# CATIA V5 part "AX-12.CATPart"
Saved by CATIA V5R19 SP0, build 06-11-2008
Part number: DX124_DUMMY
Revision: 27
Definition: design
Nomenclature: DX124_DUMMY
Source: made
Description: NOT SPECIFIED
Bounding box of the stored display mesh (mm): x -16 to 16, y -38.5 to 11.5, z -19 to 21.7
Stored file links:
  C:\Users\Rémi\Documents\BTS CPI\Projet 04- Guitar Elec\Maquette 3D\Moteur\AX-12.CATPart
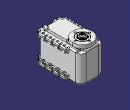
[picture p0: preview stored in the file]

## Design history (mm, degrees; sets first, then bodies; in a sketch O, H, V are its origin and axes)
Set1
  DatumSurface1 "CURVE_BOUNDED_SURFACE #7207"
  DatumSurface2 "CURVE_BOUNDED_SURFACE #7250"
  DatumSurface3 "CURVE_BOUNDED_SURFACE #7292"
  DatumSurface4 "CURVE_BOUNDED_SURFACE #7334"
  DatumSurface5 "CURVE_BOUNDED_SURFACE #7375"
  DatumSurface6 "CURVE_BOUNDED_SURFACE #7451"
  DatumSurface7 "CURVE_BOUNDED_SURFACE #7526"
  DatumSurface8 "CURVE_BOUNDED_SURFACE #7737"
  DatumSurface9 "CURVE_BOUNDED_SURFACE #7833"
  DatumSurface10 "CURVE_BOUNDED_SURFACE #7875"
  DatumSurface11 "CURVE_BOUNDED_SURFACE #7970"
  DatumSurface12 "CURVE_BOUNDED_SURFACE #8046"
  DatumSurface13 "CURVE_BOUNDED_SURFACE #8088"
  DatumSurface14 "CURVE_BOUNDED_SURFACE #8129"
  DatumSurface15 "CURVE_BOUNDED_SURFACE #8204"
  DatumSurface16 "CURVE_BOUNDED_SURFACE #8245"
  DatumSurface17 "CURVE_BOUNDED_SURFACE #8286"
  DatumSurface18 "CURVE_BOUNDED_SURFACE #8361"
  DatumSurface19 "CURVE_BOUNDED_SURFACE #9345"
  DatumSurface20 "CURVE_BOUNDED_SURFACE #9397"
  DatumSurface21 "CURVE_BOUNDED_SURFACE #9488"
  DatumSurface22 "CURVE_BOUNDED_SURFACE #9579"
  DatumSurface23 "CURVE_BOUNDED_SURFACE #9670"
  DatumSurface24 "CURVE_BOUNDED_SURFACE #9761"
  DatumSurface25 "CURVE_BOUNDED_SURFACE #9851"
  DatumSurface26 "CURVE_BOUNDED_SURFACE #9929"
  DatumSurface27 "CURVE_BOUNDED_SURFACE #10008"
  DatumSurface28 "CURVE_BOUNDED_SURFACE #10058"
  DatumSurface29 "CURVE_BOUNDED_SURFACE #10131"
  DatumSurface30 "CURVE_BOUNDED_SURFACE #10210"
  DatumSurface31 "CURVE_BOUNDED_SURFACE #10289"
  DatumSurface32 "CURVE_BOUNDED_SURFACE #10368"
  DatumSurface33 "CURVE_BOUNDED_SURFACE #10429"
  DatumSurface34 "CURVE_BOUNDED_SURFACE #10500"
  DatumSurface35 "CURVE_BOUNDED_SURFACE #10573"
  DatumSurface36 "CURVE_BOUNDED_SURFACE #10652"
  DatumSurface37 "CURVE_BOUNDED_SURFACE #10731"
  DatumSurface38 "CURVE_BOUNDED_SURFACE #10810"
  DatumSurface39 "CURVE_BOUNDED_SURFACE #10871"
  DatumSurface40 "CURVE_BOUNDED_SURFACE #10943"
  DatumSurface41 "CURVE_BOUNDED_SURFACE #10985"
  DatumSurface42 "CURVE_BOUNDED_SURFACE #11027"
  DatumSurface43 "CURVE_BOUNDED_SURFACE #11077"
  DatumSurface44 "CURVE_BOUNDED_SURFACE #11153"
  DatumSurface45 "CURVE_BOUNDED_SURFACE #11230"
  DatumSurface46 "CURVE_BOUNDED_SURFACE #11307"
  DatumSurface47 "CURVE_BOUNDED_SURFACE #11384"
  DatumSurface48 "CURVE_BOUNDED_SURFACE #11460"
  DatumSurface49 "CURVE_BOUNDED_SURFACE #11958"
  DatumSurface50 "CURVE_BOUNDED_SURFACE #12121"
  DatumSurface51 "CURVE_BOUNDED_SURFACE #12250"
  DatumSurface52 "CURVE_BOUNDED_SURFACE #12382"
  DatumSurface53 "CURVE_BOUNDED_SURFACE #12492"
  DatumSurface54 "CURVE_BOUNDED_SURFACE #12532"
  DatumSurface55 "CURVE_BOUNDED_SURFACE #12571"
  DatumSurface56 "CURVE_BOUNDED_SURFACE #12683"
  DatumSurface57 "CURVE_BOUNDED_SURFACE #12743"
  DatumSurface58 "CURVE_BOUNDED_SURFACE #12800"
  DatumSurface59 "CURVE_BOUNDED_SURFACE #12871"
  DatumSurface60 "CURVE_BOUNDED_SURFACE #12949"
  DatumSurface61 "CURVE_BOUNDED_SURFACE #13027"
  DatumSurface62 "CURVE_BOUNDED_SURFACE #13105"
  DatumSurface63 "CURVE_BOUNDED_SURFACE #13165"
  DatumSurface64 "CURVE_BOUNDED_SURFACE #13236"
  DatumSurface65 "CURVE_BOUNDED_SURFACE #13309"
  DatumSurface66 "CURVE_BOUNDED_SURFACE #13388"
  DatumSurface67 "CURVE_BOUNDED_SURFACE #13467"
  DatumSurface68 "CURVE_BOUNDED_SURFACE #13546"
  DatumSurface69 "CURVE_BOUNDED_SURFACE #13607"
  DatumSurface70 "CURVE_BOUNDED_SURFACE #13679"
  DatumSurface71 "CURVE_BOUNDED_SURFACE #13721"
  DatumSurface72 "CURVE_BOUNDED_SURFACE #13761"
  DatumSurface73 "CURVE_BOUNDED_SURFACE #13812"
  DatumSurface74 "CURVE_BOUNDED_SURFACE #13888"
  DatumSurface75 "CURVE_BOUNDED_SURFACE #13965"
  DatumSurface76 "CURVE_BOUNDED_SURFACE #14042"
  DatumSurface77 "CURVE_BOUNDED_SURFACE #14119"
  DatumSurface78 "CURVE_BOUNDED_SURFACE #14208"
  DatumSurface79 "CURVE_BOUNDED_SURFACE #14298"
  DatumSurface80 "CURVE_BOUNDED_SURFACE #14388"
  DatumSurface81 "CURVE_BOUNDED_SURFACE #14478"
  DatumSurface82 "CURVE_BOUNDED_SURFACE #14568"
  DatumSurface83 "CURVE_BOUNDED_SURFACE #14617"
  DatumSurface84 "CURVE_BOUNDED_SURFACE #14690"
  DatumSurface85 "CURVE_BOUNDED_SURFACE #14765"
  DatumSurface86 "CURVE_BOUNDED_SURFACE #14840"
  DatumSurface87 "CURVE_BOUNDED_SURFACE #14915"
  DatumSurface88 "CURVE_BOUNDED_SURFACE #14989"
  DatumSurface89 "CURVE_BOUNDED_SURFACE #15029"
  DatumSurface90 "CURVE_BOUNDED_SURFACE #15068"
  DatumSurface91 "CURVE_BOUNDED_SURFACE #15118"
  DatumSurface92 "CURVE_BOUNDED_SURFACE #15170"
  DatumSurface93 "CURVE_BOUNDED_SURFACE #15199"
  DatumSurface94 "CURVE_BOUNDED_SURFACE #15229"
  DatumSurface95 "CURVE_BOUNDED_SURFACE #15259"
  DatumSurface96 "CURVE_BOUNDED_SURFACE #15289"
  DatumSurface97 "CURVE_BOUNDED_SURFACE #15320"
  DatumSurface98 "CURVE_BOUNDED_SURFACE #15369"
  DatumSurface99 "CURVE_BOUNDED_SURFACE #15421"
  DatumSurface100 "CURVE_BOUNDED_SURFACE #15471"
  DatumSurface101 "CURVE_BOUNDED_SURFACE #16436"
  DatumSurface102 "CURVE_BOUNDED_SURFACE #16487"
  DatumSurface103 "CURVE_BOUNDED_SURFACE #16536"
  DatumSurface104 "CURVE_BOUNDED_SURFACE #16585"
  DatumSurface105 "CURVE_BOUNDED_SURFACE #16636"
  DatumSurface106 "CURVE_BOUNDED_SURFACE #16685"
  DatumSurface107 "CURVE_BOUNDED_SURFACE #16734"
  DatumSurface108 "CURVE_BOUNDED_SURFACE #16783"
  DatumSurface109 "CURVE_BOUNDED_SURFACE #16834"
  DatumSurface110 "CURVE_BOUNDED_SURFACE #16887"
  DatumSurface111 "CURVE_BOUNDED_SURFACE #16940"
  DatumSurface112 "CURVE_BOUNDED_SURFACE #16992"
  DatumSurface113 "CURVE_BOUNDED_SURFACE #17083"
  DatumSurface114 "CURVE_BOUNDED_SURFACE #17174"
  DatumSurface115 "CURVE_BOUNDED_SURFACE #17265"
  DatumSurface116 "CURVE_BOUNDED_SURFACE #17355"
  DatumSurface117 "CURVE_BOUNDED_SURFACE #17446"
  DatumSurface118 "CURVE_BOUNDED_SURFACE #17522"
  DatumSurface119 "CURVE_BOUNDED_SURFACE #17598"
  DatumSurface120 "CURVE_BOUNDED_SURFACE #17674"
  DatumSurface121 "CURVE_BOUNDED_SURFACE #17750"
  DatumSurface122 "CURVE_BOUNDED_SURFACE #17799"
  DatumSurface123 "CURVE_BOUNDED_SURFACE #17840"
  DatumSurface124 "CURVE_BOUNDED_SURFACE #17915"
  DatumSurface125 "CURVE_BOUNDED_SURFACE #17992"
  DatumSurface126 "CURVE_BOUNDED_SURFACE #18069"
  DatumSurface127 "CURVE_BOUNDED_SURFACE #18146"
  DatumSurface128 "CURVE_BOUNDED_SURFACE #18221"
  DatumSurface129 "CURVE_BOUNDED_SURFACE #18714"
  DatumSurface130 "CURVE_BOUNDED_SURFACE #18789"
  DatumSurface131 "CURVE_BOUNDED_SURFACE #18864"
  DatumSurface132 "CURVE_BOUNDED_SURFACE #18939"
  DatumSurface133 "CURVE_BOUNDED_SURFACE #19014"
  DatumSurface134 "CURVE_BOUNDED_SURFACE #19089"
  DatumSurface135 "CURVE_BOUNDED_SURFACE #19139"
  DatumSurface136 "CURVE_BOUNDED_SURFACE #19215"
  DatumSurface137 "CURVE_BOUNDED_SURFACE #19292"
  DatumSurface138 "CURVE_BOUNDED_SURFACE #19369"
  DatumSurface139 "CURVE_BOUNDED_SURFACE #19446"
  DatumSurface140 "CURVE_BOUNDED_SURFACE #19536"
  DatumSurface141 "CURVE_BOUNDED_SURFACE #19625"
  DatumSurface142 "CURVE_BOUNDED_SURFACE #19715"
  DatumSurface143 "CURVE_BOUNDED_SURFACE #19805"
  DatumSurface144 "CURVE_BOUNDED_SURFACE #19895"
  DatumSurface145 "CURVE_BOUNDED_SURFACE #19943"
  DatumSurface146 "CURVE_BOUNDED_SURFACE #19983"
  DatumSurface147 "CURVE_BOUNDED_SURFACE #20023"
  DatumSurface148 "CURVE_BOUNDED_SURFACE #20128"
  DatumSurface149 "CURVE_BOUNDED_SURFACE #20168"
  DatumSurface150 "CURVE_BOUNDED_SURFACE #20208"
  DatumSurface151 "CURVE_BOUNDED_SURFACE #20256"
  DatumSurface152 "CURVE_BOUNDED_SURFACE #20330"
  DatumSurface153 "CURVE_BOUNDED_SURFACE #20404"
  DatumSurface154 "CURVE_BOUNDED_SURFACE #20444"
  DatumSurface155 "CURVE_BOUNDED_SURFACE #20502"
  DatumSurface156 "CURVE_BOUNDED_SURFACE #20559"
  DatumSurface157 "CURVE_BOUNDED_SURFACE #20598"
  DatumSurface158 "CURVE_BOUNDED_SURFACE #20639"
  DatumSurface159 "CURVE_BOUNDED_SURFACE #20680"
  DatumSurface160 "CURVE_BOUNDED_SURFACE #20730"
  DatumSurface161 "CURVE_BOUNDED_SURFACE #20769"
  DatumSurface162 "CURVE_BOUNDED_SURFACE #20819"
  DatumSurface163 "CURVE_BOUNDED_SURFACE #20858"
  DatumSurface164 "CURVE_BOUNDED_SURFACE #20906"
  DatumSurface165 "CURVE_BOUNDED_SURFACE #20946"
  DatumSurface166 "CURVE_BOUNDED_SURFACE #20985"
  DatumSurface167 "CURVE_BOUNDED_SURFACE #21043"
  DatumSurface168 "CURVE_BOUNDED_SURFACE #21101"
  DatumSurface169 "CURVE_BOUNDED_SURFACE #21153"
  DatumSurface170 "CURVE_BOUNDED_SURFACE #21311"
  DatumSurface171 "CURVE_BOUNDED_SURFACE #21352"
  DatumSurface172 "CURVE_BOUNDED_SURFACE #21394"
  DatumSurface173 "CURVE_BOUNDED_SURFACE #21435"
  DatumSurface174 "CURVE_BOUNDED_SURFACE #21486"
  DatumSurface175 "CURVE_BOUNDED_SURFACE #21542"
  DatumSurface176 "CURVE_BOUNDED_SURFACE #21599"
  DatumSurface177 "CURVE_BOUNDED_SURFACE #21639"
  DatumSurface178 "CURVE_BOUNDED_SURFACE #21696"
  DatumSurface179 "CURVE_BOUNDED_SURFACE #21754"
  DatumSurface180 "CURVE_BOUNDED_SURFACE #21795"
  DatumSurface181 "CURVE_BOUNDED_SURFACE #21852"
  DatumSurface182 "CURVE_BOUNDED_SURFACE #21910"
  DatumSurface183 "CURVE_BOUNDED_SURFACE #21950"
  DatumSurface184 "CURVE_BOUNDED_SURFACE #22007"
  DatumSurface185 "CURVE_BOUNDED_SURFACE #22065"
  DatumSurface186 "CURVE_BOUNDED_SURFACE #22106"
  DatumSurface187 "CURVE_BOUNDED_SURFACE #22163"
  DatumSurface188 "CURVE_BOUNDED_SURFACE #22221"
  DatumSurface189 "CURVE_BOUNDED_SURFACE #22261"
  DatumSurface190 "CURVE_BOUNDED_SURFACE #22318"
  DatumSurface191 "CURVE_BOUNDED_SURFACE #22376"
  DatumSurface192 "CURVE_BOUNDED_SURFACE #22417"
  DatumSurface193 "CURVE_BOUNDED_SURFACE #22474"
  DatumSurface194 "CURVE_BOUNDED_SURFACE #22532"
  DatumSurface195 "CURVE_BOUNDED_SURFACE #22572"
  DatumSurface196 "CURVE_BOUNDED_SURFACE #22630"
  DatumSurface197 "CURVE_BOUNDED_SURFACE #22689"
  DatumSurface198 "CURVE_BOUNDED_SURFACE #22746"
  DatumSurface199 "CURVE_BOUNDED_SURFACE #22804"
  DatumSurface200 "CURVE_BOUNDED_SURFACE #22845"
  DatumSurface201 "CURVE_BOUNDED_SURFACE #22907"
  DatumSurface202 "CURVE_BOUNDED_SURFACE #22955"
  DatumSurface203 "CURVE_BOUNDED_SURFACE #23044"
  DatumSurface204 "CURVE_BOUNDED_SURFACE #23111"
  DatumSurface205 "CURVE_BOUNDED_SURFACE #23158"
  DatumSurface206 "CURVE_BOUNDED_SURFACE #23205"
  DatumSurface207 "CURVE_BOUNDED_SURFACE #23259"
  DatumSurface208 "CURVE_BOUNDED_SURFACE #23314"
  DatumSurface209 "CURVE_BOUNDED_SURFACE #23383"
  DatumSurface210 "CURVE_BOUNDED_SURFACE #23505"
  DatumSurface211 "CURVE_BOUNDED_SURFACE #23547"
  DatumSurface212 "CURVE_BOUNDED_SURFACE #23589"
  DatumSurface213 "CURVE_BOUNDED_SURFACE #23647"
  DatumSurface214 "CURVE_BOUNDED_SURFACE #23827"
  DatumSurface215 "CURVE_BOUNDED_SURFACE #23877"
  DatumSurface216 "CURVE_BOUNDED_SURFACE #23932"
  DatumSurface217 "CURVE_BOUNDED_SURFACE #23980"
  DatumSurface218 "CURVE_BOUNDED_SURFACE #24042"
  DatumSurface219 "CURVE_BOUNDED_SURFACE #24131"
  DatumSurface220 "CURVE_BOUNDED_SURFACE #24179"
  DatumSurface221 "CURVE_BOUNDED_SURFACE #24241"
  DatumSurface222 "CURVE_BOUNDED_SURFACE #24281"
  DatumSurface223 "CURVE_BOUNDED_SURFACE #24322"
  DatumSurface224 "CURVE_BOUNDED_SURFACE #24361"
  DatumSurface225 "CURVE_BOUNDED_SURFACE #24401"
  DatumSurface226 "CURVE_BOUNDED_SURFACE #24462"
  DatumSurface227 "CURVE_BOUNDED_SURFACE #24510"
  DatumSurface228 "CURVE_BOUNDED_SURFACE #24595"
  DatumSurface229 "CURVE_BOUNDED_SURFACE #24660"
  DatumSurface230 "CURVE_BOUNDED_SURFACE #24717"
  DatumSurface231 "CURVE_BOUNDED_SURFACE #24765"
  DatumSurface232 "CURVE_BOUNDED_SURFACE #24849"
  DatumSurface233 "CURVE_BOUNDED_SURFACE #24897"
  DatumSurface234 "CURVE_BOUNDED_SURFACE #24959"
  DatumSurface235 "CURVE_BOUNDED_SURFACE #24999"
  DatumSurface236 "CURVE_BOUNDED_SURFACE #25038"
  DatumSurface237 "CURVE_BOUNDED_SURFACE #25077"
  DatumSurface238 "CURVE_BOUNDED_SURFACE #25131"
  DatumSurface239 "CURVE_BOUNDED_SURFACE #25179"
  DatumSurface240 "CURVE_BOUNDED_SURFACE #25241"
  DatumSurface241 "CURVE_BOUNDED_SURFACE #25296"
  DatumSurface242 "CURVE_BOUNDED_SURFACE #25343"
  DatumSurface243 "CURVE_BOUNDED_SURFACE #25395"
  DatumSurface244 "CURVE_BOUNDED_SURFACE #25445"
  DatumSurface245 "CURVE_BOUNDED_SURFACE #25705"
  DatumSurface246 "CURVE_BOUNDED_SURFACE #25761"
  DatumSurface247 "CURVE_BOUNDED_SURFACE #26022"
  DatumSurface248 "CURVE_BOUNDED_SURFACE #26114"
  DatumSurface249 "CURVE_BOUNDED_SURFACE #26167"
  DatumSurface250 "CURVE_BOUNDED_SURFACE #26219"
  DatumSurface251 "CURVE_BOUNDED_SURFACE #26269"
  DatumSurface252 "CURVE_BOUNDED_SURFACE #26361"
  DatumSurface253 "CURVE_BOUNDED_SURFACE #26412"
  DatumSurface254 "CURVE_BOUNDED_SURFACE #26461"
  DatumSurface255 "CURVE_BOUNDED_SURFACE #26513"
  DatumSurface256 "CURVE_BOUNDED_SURFACE #26563"
  DatumSurface257 "CURVE_BOUNDED_SURFACE #26606"
  DatumSurface258 "CURVE_BOUNDED_SURFACE #26657"
  DatumSurface259 "CURVE_BOUNDED_SURFACE #26706"
  DatumSurface260 "CURVE_BOUNDED_SURFACE #26757"
  DatumSurface261 "CURVE_BOUNDED_SURFACE #26806"
  DatumSurface262 "CURVE_BOUNDED_SURFACE #26857"
  DatumSurface263 "CURVE_BOUNDED_SURFACE #26906"
  DatumSurface264 "CURVE_BOUNDED_SURFACE #26957"
  DatumSurface265 "CURVE_BOUNDED_SURFACE #27006"
  DatumSurface266 "CURVE_BOUNDED_SURFACE #27073"
  DatumSurface267 "CURVE_BOUNDED_SURFACE #27139"
  DatumSurface268 "CURVE_BOUNDED_SURFACE #27179"
  DatumSurface269 "CURVE_BOUNDED_SURFACE #27244"
  DatumSurface270 "CURVE_BOUNDED_SURFACE #27284"
  DatumSurface271 "CURVE_BOUNDED_SURFACE #27343"
  DatumSurface272 "CURVE_BOUNDED_SURFACE #27400"
  DatumSurface273 "CURVE_BOUNDED_SURFACE #27441"
  DatumSurface274 "CURVE_BOUNDED_SURFACE #27499"
  DatumSurface275 "CURVE_BOUNDED_SURFACE #27557"
  DatumSurface276 "CURVE_BOUNDED_SURFACE #27598"
  DatumSurface277 "CURVE_BOUNDED_SURFACE #27656"
  DatumSurface278 "CURVE_BOUNDED_SURFACE #27714"
  DatumSurface279 "CURVE_BOUNDED_SURFACE #27755"
  DatumSurface280 "CURVE_BOUNDED_SURFACE #27813"
  DatumSurface281 "CURVE_BOUNDED_SURFACE #27871"
  DatumSurface282 "CURVE_BOUNDED_SURFACE #27912"
  DatumSurface283 "CURVE_BOUNDED_SURFACE #27970"
  DatumSurface284 "CURVE_BOUNDED_SURFACE #28028"
  DatumSurface285 "CURVE_BOUNDED_SURFACE #28069"
  DatumSurface286 "CURVE_BOUNDED_SURFACE #28127"
  DatumSurface287 "CURVE_BOUNDED_SURFACE #28185"
  DatumSurface288 "CURVE_BOUNDED_SURFACE #28226"
  DatumSurface289 "CURVE_BOUNDED_SURFACE #28284"
  DatumSurface290 "CURVE_BOUNDED_SURFACE #28342"
  DatumSurface291 "CURVE_BOUNDED_SURFACE #28393"
  DatumSurface292 "CURVE_BOUNDED_SURFACE #28433"
  DatumSurface293 "CURVE_BOUNDED_SURFACE #28472"
  DatumSurface294 "CURVE_BOUNDED_SURFACE #28513"
  DatumSurface295 "CURVE_BOUNDED_SURFACE #28563"
  DatumSurface296 "CURVE_BOUNDED_SURFACE #28602"
  DatumSurface297 "CURVE_BOUNDED_SURFACE #28674"
  DatumSurface298 "CURVE_BOUNDED_SURFACE #28747"
  DatumSurface299 "CURVE_BOUNDED_SURFACE #28820"
  DatumSurface300 "CURVE_BOUNDED_SURFACE #28894"
  DatumSurface301 "CURVE_BOUNDED_SURFACE #28942"
  DatumSurface302 "CURVE_BOUNDED_SURFACE #28982"
  DatumSurface303 "CURVE_BOUNDED_SURFACE #29021"
  DatumSurface304 "CURVE_BOUNDED_SURFACE #29069"
  DatumSurface305 "CURVE_BOUNDED_SURFACE #29109"
  DatumSurface306 "CURVE_BOUNDED_SURFACE #29149"
  DatumSurface307 "CURVE_BOUNDED_SURFACE #29196"
  DatumSurface308 "CURVE_BOUNDED_SURFACE #29244"
  DatumSurface309 "CURVE_BOUNDED_SURFACE #29284"
  DatumSurface310 "CURVE_BOUNDED_SURFACE #29324"
  DatumSurface311 "CURVE_BOUNDED_SURFACE #29371"
  DatumSurface312 "CURVE_BOUNDED_SURFACE #29419"
  DatumSurface313 "CURVE_BOUNDED_SURFACE #29459"
  DatumSurface314 "CURVE_BOUNDED_SURFACE #29499"
  DatumSurface315 "CURVE_BOUNDED_SURFACE #29546"
  DatumSurface316 "CURVE_BOUNDED_SURFACE #29585"
  DatumSurface317 "CURVE_BOUNDED_SURFACE #29624"
  DatumSurface318 "CURVE_BOUNDED_SURFACE #29663"
  DatumSurface319 "CURVE_BOUNDED_SURFACE #29703"
  DatumSurface320 "CURVE_BOUNDED_SURFACE #29742"
  DatumSurface321 "CURVE_BOUNDED_SURFACE #29781"
  DatumSurface322 "CURVE_BOUNDED_SURFACE #29820"
  DatumSurface323 "CURVE_BOUNDED_SURFACE #29860"
  DatumSurface324 "CURVE_BOUNDED_SURFACE #29899"
  DatumSurface325 "CURVE_BOUNDED_SURFACE #29938"
  DatumSurface326 "CURVE_BOUNDED_SURFACE #29977"
  DatumSurface327 "CURVE_BOUNDED_SURFACE #30017"
  DatumSurface328 "CURVE_BOUNDED_SURFACE #30056"
  DatumSurface329 "CURVE_BOUNDED_SURFACE #30095"
  DatumSurface330 "CURVE_BOUNDED_SURFACE #30134"
  DatumSurface331 "CURVE_BOUNDED_SURFACE #30174"
  DatumSurface332 "CURVE_BOUNDED_SURFACE #30213"
  DatumSurface333 "CURVE_BOUNDED_SURFACE #30252"
  DatumSurface334 "CURVE_BOUNDED_SURFACE #30291"
  DatumSurface335 "CURVE_BOUNDED_SURFACE #30331"
  DatumSurface336 "CURVE_BOUNDED_SURFACE #30370"
  DatumSurface337 "CURVE_BOUNDED_SURFACE #30409"
  DatumSurface338 "CURVE_BOUNDED_SURFACE #30448"
  DatumSurface339 "CURVE_BOUNDED_SURFACE #30488"
  DatumSurface340 "CURVE_BOUNDED_SURFACE #30527"
  DatumSurface341 "CURVE_BOUNDED_SURFACE #30566"
  DatumSurface342 "CURVE_BOUNDED_SURFACE #30615"
  DatumSurface343 "CURVE_BOUNDED_SURFACE #30654"
  DatumSurface344 "CURVE_BOUNDED_SURFACE #30705"
  DatumSurface345 "CURVE_BOUNDED_SURFACE #30745"
  DatumSurface346 "CURVE_BOUNDED_SURFACE #30785"
  DatumSurface347 "CURVE_BOUNDED_SURFACE #30824"
  DatumSurface348 "CURVE_BOUNDED_SURFACE #30863"
  DatumSurface349 "CURVE_BOUNDED_SURFACE #30903"
  DatumSurface350 "CURVE_BOUNDED_SURFACE #30960"
  DatumSurface351 "CURVE_BOUNDED_SURFACE #31016"
  DatumSurface352 "CURVE_BOUNDED_SURFACE #31055"
  DatumSurface353 "CURVE_BOUNDED_SURFACE #31094"
  DatumSurface354 "CURVE_BOUNDED_SURFACE #31133"
  DatumSurface355 "CURVE_BOUNDED_SURFACE #31181"
  DatumSurface356 "CURVE_BOUNDED_SURFACE #31221"
  DatumSurface357 "CURVE_BOUNDED_SURFACE #31260"
  DatumSurface358 "CURVE_BOUNDED_SURFACE #31308"
  DatumSurface359 "CURVE_BOUNDED_SURFACE #31348"
  DatumSurface360 "CURVE_BOUNDED_SURFACE #31388"
  DatumSurface361 "CURVE_BOUNDED_SURFACE #31435"
  DatumSurface362 "CURVE_BOUNDED_SURFACE #31483"
  DatumSurface363 "CURVE_BOUNDED_SURFACE #31523"
  DatumSurface364 "CURVE_BOUNDED_SURFACE #31563"
  DatumSurface365 "CURVE_BOUNDED_SURFACE #31610"
  DatumSurface366 "CURVE_BOUNDED_SURFACE #31658"
  DatumSurface367 "CURVE_BOUNDED_SURFACE #31698"
  DatumSurface368 "CURVE_BOUNDED_SURFACE #31738"
  DatumSurface369 "CURVE_BOUNDED_SURFACE #31785"
  DatumSurface370 "CURVE_BOUNDED_SURFACE #31836"
  DatumSurface371 "CURVE_BOUNDED_SURFACE #31886"
  DatumSurface372 "CURVE_BOUNDED_SURFACE #31935"
  DatumSurface373 "CURVE_BOUNDED_SURFACE #31965"
  DatumSurface374 "CURVE_BOUNDED_SURFACE #31995"
  DatumSurface375 "CURVE_BOUNDED_SURFACE #32025"
  DatumSurface376 "CURVE_BOUNDED_SURFACE #32054"
  DatumSurface377 "CURVE_BOUNDED_SURFACE #32085"
  DatumSurface378 "CURVE_BOUNDED_SURFACE #32134"
  DatumSurface379 "CURVE_BOUNDED_SURFACE #32185"
  DatumSurface380 "CURVE_BOUNDED_SURFACE #32234"
  DatumSurface381 "CURVE_BOUNDED_SURFACE #32283"
  DatumSurface382 "CURVE_BOUNDED_SURFACE #32334"
  DatumSurface383 "CURVE_BOUNDED_SURFACE #32383"
  DatumSurface384 "CURVE_BOUNDED_SURFACE #32432"
  DatumSurface385 "CURVE_BOUNDED_SURFACE #32483"
  DatumSurface386 "CURVE_BOUNDED_SURFACE #32532"
  DatumSurface387 "CURVE_BOUNDED_SURFACE #32585"
  DatumSurface388 "CURVE_BOUNDED_SURFACE #32640"
  DatumSurface389 "CURVE_BOUNDED_SURFACE #32689"
  DatumSurface390 "CURVE_BOUNDED_SURFACE #32739"
  DatumSurface391 "CURVE_BOUNDED_SURFACE #32788"
  DatumSurface392 "CURVE_BOUNDED_SURFACE #32818"
  DatumSurface393 "CURVE_BOUNDED_SURFACE #32848"
  DatumSurface394 "CURVE_BOUNDED_SURFACE #32878"
  DatumSurface395 "CURVE_BOUNDED_SURFACE #32907"
  DatumSurface396 "CURVE_BOUNDED_SURFACE #32938"
  DatumSurface397 "CURVE_BOUNDED_SURFACE #32987"
  DatumSurface398 "CURVE_BOUNDED_SURFACE #33038"
  DatumSurface399 "CURVE_BOUNDED_SURFACE #33087"
  DatumSurface400 "CURVE_BOUNDED_SURFACE #33136"
  DatumSurface401 "CURVE_BOUNDED_SURFACE #33187"
  DatumSurface402 "CURVE_BOUNDED_SURFACE #33236"
  DatumSurface403 "CURVE_BOUNDED_SURFACE #33285"
  DatumSurface404 "CURVE_BOUNDED_SURFACE #33336"
  DatumSurface405 "CURVE_BOUNDED_SURFACE #33385"
  DatumSurface406 "CURVE_BOUNDED_SURFACE #33438"
  DatumSurface407 "CURVE_BOUNDED_SURFACE #33493"
  DatumSurface408 "CURVE_BOUNDED_SURFACE #33542"
  DatumSurface409 "CURVE_BOUNDED_SURFACE #33582"
  DatumSurface410 "CURVE_BOUNDED_SURFACE #33629"
  DatumSurface411 "CURVE_BOUNDED_SURFACE #33677"
  DatumSurface412 "CURVE_BOUNDED_SURFACE #33717"
  DatumSurface413 "CURVE_BOUNDED_SURFACE #33757"
  DatumSurface414 "CURVE_BOUNDED_SURFACE #33804"
  DatumSurface415 "CURVE_BOUNDED_SURFACE #33852"
  DatumSurface416 "CURVE_BOUNDED_SURFACE #33892"
  DatumSurface417 "CURVE_BOUNDED_SURFACE #33932"
  DatumSurface418 "CURVE_BOUNDED_SURFACE #33979"
  DatumSurface419 "CURVE_BOUNDED_SURFACE #34027"
  DatumSurface420 "CURVE_BOUNDED_SURFACE #34067"
  DatumSurface421 "CURVE_BOUNDED_SURFACE #34107"
  DatumSurface422 "CURVE_BOUNDED_SURFACE #34154"
  DatumSurface423 "CURVE_BOUNDED_SURFACE #34202"
  DatumSurface424 "CURVE_BOUNDED_SURFACE #34242"
  DatumSurface425 "CURVE_BOUNDED_SURFACE #34282"
  DatumSurface426 "CURVE_BOUNDED_SURFACE #34329"
  DatumSurface427 "CURVE_BOUNDED_SURFACE #34377"
  DatumSurface428 "CURVE_BOUNDED_SURFACE #34417"
  DatumSurface429 "CURVE_BOUNDED_SURFACE #34457"
  DatumSurface430 "CURVE_BOUNDED_SURFACE #34504"
  DatumSurface431 "CURVE_BOUNDED_SURFACE #34552"
  DatumSurface432 "CURVE_BOUNDED_SURFACE #34592"
  DatumSurface433 "CURVE_BOUNDED_SURFACE #34632"
  DatumSurface434 "CURVE_BOUNDED_SURFACE #34679"
  DatumSurface435 "CURVE_BOUNDED_SURFACE #34733"
  DatumSurface436 "CURVE_BOUNDED_SURFACE #34788"
  DatumSurface437 "CURVE_BOUNDED_SURFACE #34818"
  DatumSurface438 "CURVE_BOUNDED_SURFACE #34848"
  DatumSurface439 "CURVE_BOUNDED_SURFACE #34878"
  DatumSurface440 "CURVE_BOUNDED_SURFACE #34908"
  DatumSurface441 "CURVE_BOUNDED_SURFACE #34938"
  DatumSurface442 "CURVE_BOUNDED_SURFACE #34987"
  DatumSurface443 "CURVE_BOUNDED_SURFACE #35038"
  DatumSurface444 "CURVE_BOUNDED_SURFACE #35087"
  DatumSurface445 "CURVE_BOUNDED_SURFACE #35136"
  DatumSurface446 "CURVE_BOUNDED_SURFACE #35187"
  DatumSurface447 "CURVE_BOUNDED_SURFACE #35236"
  DatumSurface448 "CURVE_BOUNDED_SURFACE #35285"
  DatumSurface449 "CURVE_BOUNDED_SURFACE #35336"
  DatumSurface450 "CURVE_BOUNDED_SURFACE #35385"
  DatumSurface451 "CURVE_BOUNDED_SURFACE #35434"
  DatumSurface452 "CURVE_BOUNDED_SURFACE #35483"
  DatumSurface453 "CURVE_BOUNDED_SURFACE #35532"
  DatumSurface454 "CURVE_BOUNDED_SURFACE #35587"
  DatumSurface455 "CURVE_BOUNDED_SURFACE #35627"
  DatumSurface456 "CURVE_BOUNDED_SURFACE #35675"
  DatumSurface457 "CURVE_BOUNDED_SURFACE #35750"
  DatumSurface458 "CURVE_BOUNDED_SURFACE #35799"
  DatumSurface459 "CURVE_BOUNDED_SURFACE #35847"
  DatumSurface460 "CURVE_BOUNDED_SURFACE #35921"
  DatumSurface461 "CURVE_BOUNDED_SURFACE #36011"
  DatumSurface462 "CURVE_BOUNDED_SURFACE #36051"
  DatumSurface463 "CURVE_BOUNDED_SURFACE #36091"
  DatumSurface464 "CURVE_BOUNDED_SURFACE #36131"
  DatumSurface465 "CURVE_BOUNDED_SURFACE #36170"
  DatumSurface466 "CURVE_BOUNDED_SURFACE #36211"
  DatumSurface467 "CURVE_BOUNDED_SURFACE #36258"
  DatumSurface468 "CURVE_BOUNDED_SURFACE #36344"
  DatumSurface469 "CURVE_BOUNDED_SURFACE #36444"
  DatumSurface470 "CURVE_BOUNDED_SURFACE #36496"
  DatumSurface471 "CURVE_BOUNDED_SURFACE #36546"
  DatumSurface472 "CURVE_BOUNDED_SURFACE #36636"
  DatumSurface473 "CURVE_BOUNDED_SURFACE #36688"
  DatumSurface474 "CURVE_BOUNDED_SURFACE #36738"
  DatumSurface475 "CURVE_BOUNDED_SURFACE #36781"
  DatumSurface476 "CURVE_BOUNDED_SURFACE #36829"
  DatumSurface477 "CURVE_BOUNDED_SURFACE #36884"
  DatumSurface478 "CURVE_BOUNDED_SURFACE #36923"
  DatumSurface479 "CURVE_BOUNDED_SURFACE #36997"
  DatumSurface480 "CURVE_BOUNDED_SURFACE #37037"
  DatumSurface481 "CURVE_BOUNDED_SURFACE #37077"
  DatumSurface482 "CURVE_BOUNDED_SURFACE #37117"
  DatumSurface483 "CURVE_BOUNDED_SURFACE #37157"
  DatumSurface484 "CURVE_BOUNDED_SURFACE #37196"
  DatumSurface485 "CURVE_BOUNDED_SURFACE #37235"
  DatumSurface486 "CURVE_BOUNDED_SURFACE #37274"
  Sketch1 on DatumSurface252, origin (0, 0, 21.7), H (1, 0, 0), V (0, 1, 0)
    circle A1 centre (0, 0) radius 4
    circle A2 centre (0, 0) radius 2.8
    radius A1 = 4
    radius A2 = 2.8
Body1 (main body)
  Pad1: profile Sketch1, direction (0, 0, -1), length 0.7
  Sketch2 on DatumSurface247, origin (0, 0, 21), H (1, 0, 0), V (0, -1, 0)
    circle A1 centre (0, 0) radius 4.688
    circle A2 centre (0, 0) radius 6.5539
  Pad2: profile Sketch2, direction (0, 0, -1), length 0.7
